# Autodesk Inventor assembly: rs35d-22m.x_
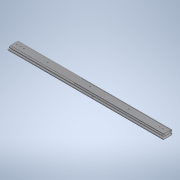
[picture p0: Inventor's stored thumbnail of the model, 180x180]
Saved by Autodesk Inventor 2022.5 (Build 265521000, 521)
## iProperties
Part Number: rs35d-22m.x_
Material: 一般
Document SubType Name: Assembly
Designer: ImaoCorp
Sending System: SOLIDWORKS 2017-2017317
MC: AMD64
MC_MODEL: Intel64 Family 6 Model 60 Stepping 3, GenuineIntel
OS: Windows_NT
FRU: Parasolid Version 29.0, build 201,  4-17-2017
FORMAT: text
GUISE: transmit
KEY: rs35d-22m
FILE: rs35d-22m.x_t
DATE: Tue Feb 05 16:29:37 2019
Author: ImaoCorp
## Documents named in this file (4)
- X:\14_SW2022-Inv2022\00_全2023-1023新製品(TCC)まで\r\rs35d-22m\RS35D-22M.iam
- X:\14_SW2022-Inv2022\00_全2023-1023新製品(TCC)まで\r\rs35d-22m\rs35d-22m_01.ipt
- X:\14_SW2022-Inv2022\00_全2023-1023新製品(TCC)まで\r\rs35d-22m\rs35d-22m_02.ipt
- X:\14_SW2022-Inv2022\00_全2023-1023新製品(TCC)まで\r\rs35d-22m\rs35d-22m_03.ipt
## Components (3 placed, 3 different names)
1. rs35d-22m_01
2. rs35d-22m_02
3. rs35d-22m_03
